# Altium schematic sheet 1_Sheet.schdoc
size 294 x 207 mm
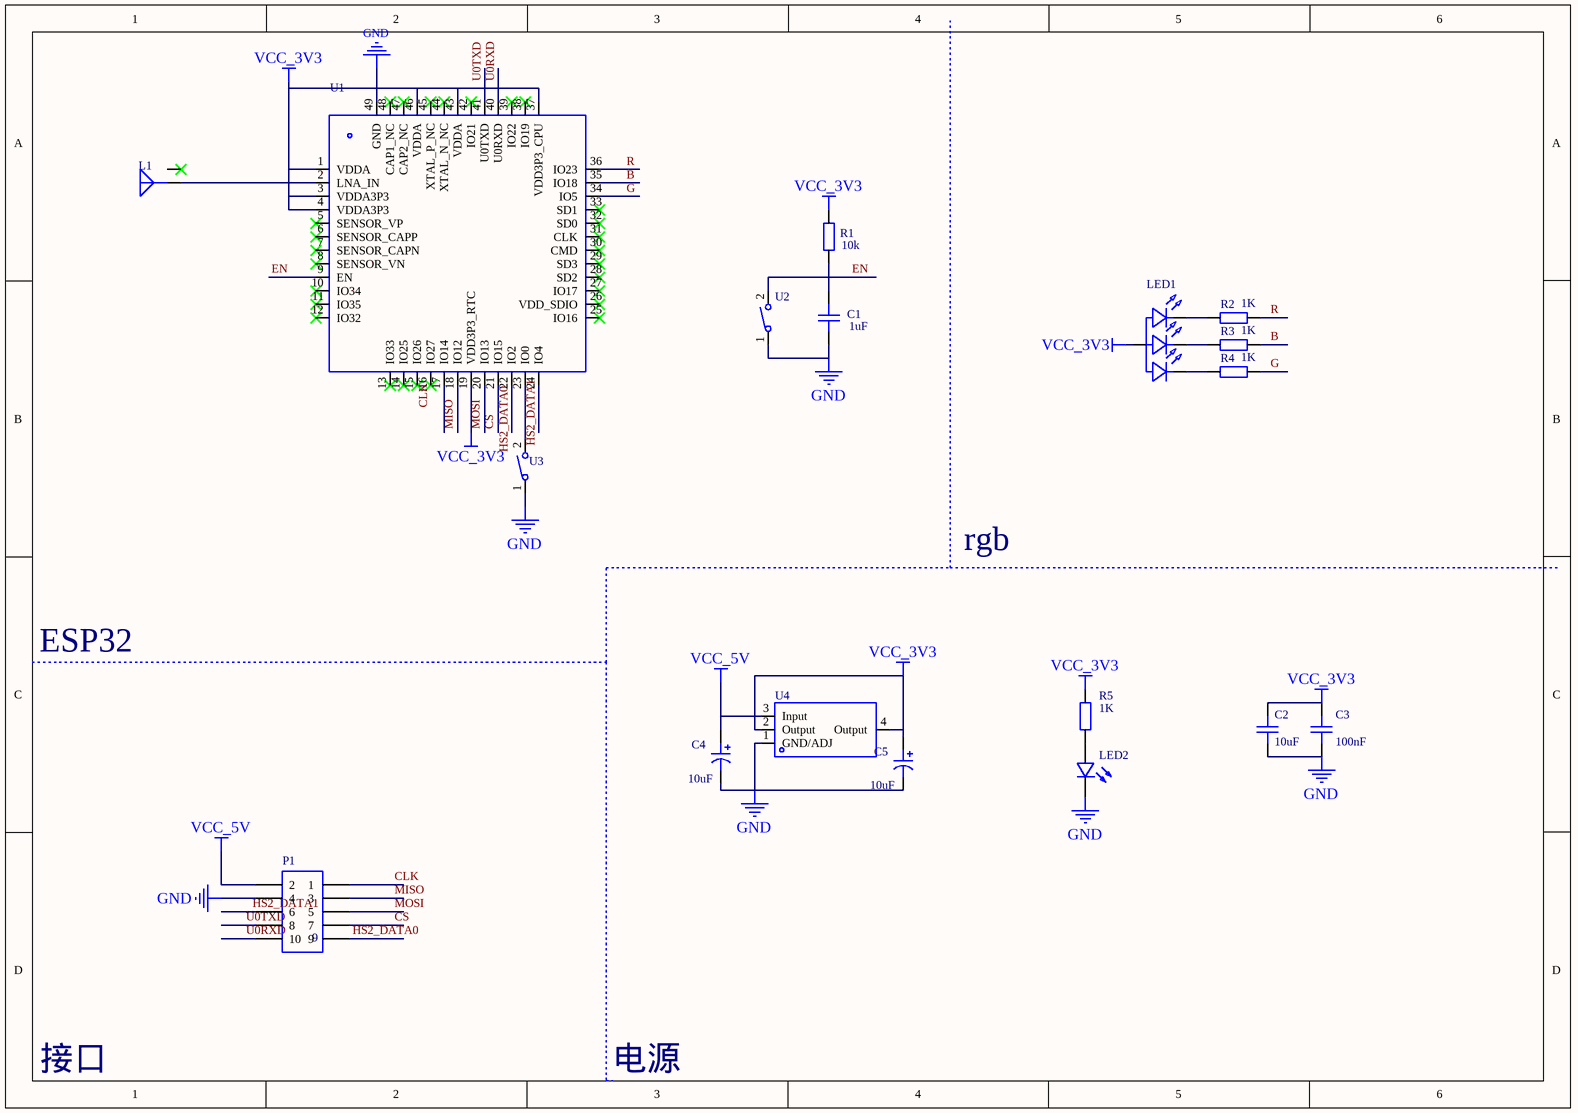
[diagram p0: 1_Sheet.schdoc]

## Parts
C1  value 1uF  [C0603_1]
C2  value 10uF  [C0603_1]
C3  value 100nF  [C0603_1]
C4  value 10uF  [CAP-SMD_L3.2-W1.6]
C5  value 10uF  [CAP-SMD_L3.2-W1.6]
L1  (no value)  [ANT2051_1]
LED1  (no value)  [LED-SMD_4P-L3.2-W2.7-TL_HL-AF-3528S39FU70GH20_1]
LED2  (no value)  [LED0603-R-RD]
P1  NAME: 9  [2*5 双面 排针_2]
R1  value 10k  [R0603_1]
R2  value 1K  [R0603_1]
R3  value 1K  [R0603_1]
R4  value 1K  [R0603_1]
R5  value 1K  [R0603_1]
U1  (no value)  [QFN-48_L7.0-W7.0-P0.50-BL-EP5.4_1]
U2  (no value)  [SW-SMD_L4.0-W3.0-LS4.8-1]
U3  (no value)  [SW-SMD_L4.0-W3.0-LS4.8-1]
U4  (no value)  [SOT-223-4_L6.5-W3.5-P2.30-LS7.0-BR_1]

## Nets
GND: C1.1 C2.1 C3.1 C4.2 C5.2 LED2.2(C) P1.4 U1.49(GND) U2.1 U3.1 U4.1(GND/ADJ)
VCC_3V3: C2.2 C3.2 C5.1 L1.1(ANT) LED1.2(A) R1.2 R5.2 U1.1(VDDA) U1.2(LNA_IN) U1.3(VDDA3P3) U1.4(VDDA3P3) U1.19(VDD3P3_RTC) U1.37(VDD3P3_CPU) U1.43(VDDA) U1.46(VDDA) U4.2(Output) U4.4(Output)
VCC_5V: C4.1 P1.2 U4.3(Input)
B: U1.35(IO18)
G: U1.34(IO5)
R: U1.36(IO23)
U0RXD: U1.40(U0RXD)
U0TXD: U1.41(U0TXD)
NetC1_2: C1.2 R1.1 U2.2
NetLED1_1: LED1.1(R) R2.1
NetLED1_3: LED1.3(G) R3.1
NetLED1_4: LED1.4(B) R4.1
NetLED2_1: LED2.1(A) R5.1
NetU1_23: U1.23(IO0) U3.2

Not connected (* = marked no-connect by the designer): L1 2*; P1 1 3 5 6 7 8 9 10; R2 2; R3 2; R4 2; U1 5(SENSOR_VP)* 6(SENSOR_CAPP)* 7(SENSOR_CAPN)* 8(SENSOR_VN)* 9(EN) 10(IO34)* 11(IO35)* 12(IO32)* 13(IO33)* 14(IO25)* 15(IO26)* 16(IO27)* 17(IO14) 18(IO12) 20(IO13) 21(IO15) 22(IO2) 24(IO4) 25(IO16)* 26(VDD_SDIO)* 27(IO17)* 28(SD2)* 29(SD3)* 30(CMD)* 31(CLK)* 32(SD0)* 33(SD1)* 38(IO19)* 39(IO22)* 42(IO21)* 44(XTAL_N_NC)* 45(XTAL_P_NC)* 47(CAP2_NC)* 48(CAP1_NC)*

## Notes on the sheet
- rgb
- ESP32
- 接口
- 电源
- Labels drawn without touching a wire or pin: B, CLK, CS, EN, G, HS2_DATA0, HS2_DATA1, MISO, MOSI, R, U0RXD, U0TXD

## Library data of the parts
C1-C3 = CC0603KRX7R9BB104: Manufacturer: YAGEO(国巨); Add into BOM: yes; Tolerance: ±10%; Voltage Rated: 50V; Temperature Coefficient: X7R; Description: 容值:100nF;精度:±10%;额定电压:50V;温度系数:X7R;
C4 C5 = CA45-A-16V-22uF-K: Manufacturer: CEC(振华新云); Add into BOM: yes; Tolerance: ±10%; Rated Voltage: 16V; Equivalent Series Resistance(ESR): 6@100kHz; Description: 容值:22uF;精度:±10%;额定电压:16V;等效串联电阻:6@100kHz;工作温度:-55~+125;
L1 = AN2051-245_1: Manufacturer: rainsun台湾霖昱微; Add into BOM: yes; Frequency Range: 2.45GHz; Description: 小体积，高增益，WIFI，蓝牙，zigBee 2.4G天线
LED1 = HL-AF-3528S39FU70GH203BC-A-S1-HL_1: Manufacturer: HONGLITRONIC(鸿利光电); Add into BOM: yes; Illumination Color: RGB三色; Luminous Intensity (IF=20mA): 350mcd红,1300mcd绿,270mcd蓝@20mA; Dominant Wavelength / Coordinate rank: 617nm627nm红,515~525nm绿,464~474nm蓝; Vf - Forward Voltage: 2V红,3V绿,3V蓝; Description: 照明颜色:RGB三色;色温 - CCT（K）:-;主波长/色坐标:617nm627nm红,515~525nm绿,464~474nm蓝;正向电压（Vf）:2V红,3V绿,3V蓝;
LED2 = 19-217/R6C-AL1M2VY/3T: Manufacturer: EVERLIGHT(台湾亿光); Add into BOM: yes; Emitted Color: 红灯; Lens Color: 无色透明; Dominant Wavelength: 617.5nm; Peak Wavelength: 632nm; Forward Current: 5mA; Forward Voltage (VF): 2.2V; Luminous Intensity: 28.5mcd; Power Dissipation: 60mW; Viewing Angle: 120°; Description: 发光颜色:红灯;二极管配置:-;透镜颜色:无色透明;主波长:617.5nm;峰值波长:632nm;色温:-;光通量(25时):-;测试电流:5mA;正向电压(VF):2.2V;发光强度:28.5mcd;功率:60mW;发光角度:120°;安装方式:-;工作温度:-40~+85;
P1 = M_2.54_2*5 双面排针: Symbol: M_2.54_2*5 双面_1; Convert to PCB: yes
R1-R5 = TR0603B10K0P0525Z: Manufacturer: EVER OHMS(天二科技); Symbol: TR0603B10KP05250.1W; Add into BOM: yes; Tolerance: ±0.1%; Power(Watts): 100mW; Temperature Coefficient: ±25ppm/; Overload Voltage (Max): 75V; Description: 电阻类型:薄膜电阻;阻值:10k;精度:±0.1%;功率:100mW;温度系数:±25ppm/;最大工作电压:75V;工作温度范围:-55~+155;
U1 = ESP32-PICO-D4-V2: Add into BOM: yes; Description: ESP32-PICO-D4个人库
U2 U3 = 3*4 龟仔/微动/轻触开关: Add into BOM: yes
U4 = AMS1117-3.3_C369933: Manufacturer: KEXIN(科信); Add into BOM: yes; Output Type: 固定; Output Polarity: 正; Number of Outputs: 1; Maximum Input Voltage: 18V; Output Voltage: 3.3V; Dropout Voltage: 1.3V@800mA; Quiescent Current (Ground Current): 8mA; Output Current: 1A; Description: 输出类型:固定;输出极性:正;输出通道数:1;最大输入电压:18V;输出电压:3.3V;压差:1.3V@800mA;静态电流(地电流):8mA;输出电流:1A;电源纹波抑制比(PRSS):-;噪声:-;特性:-;工作温度:-;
